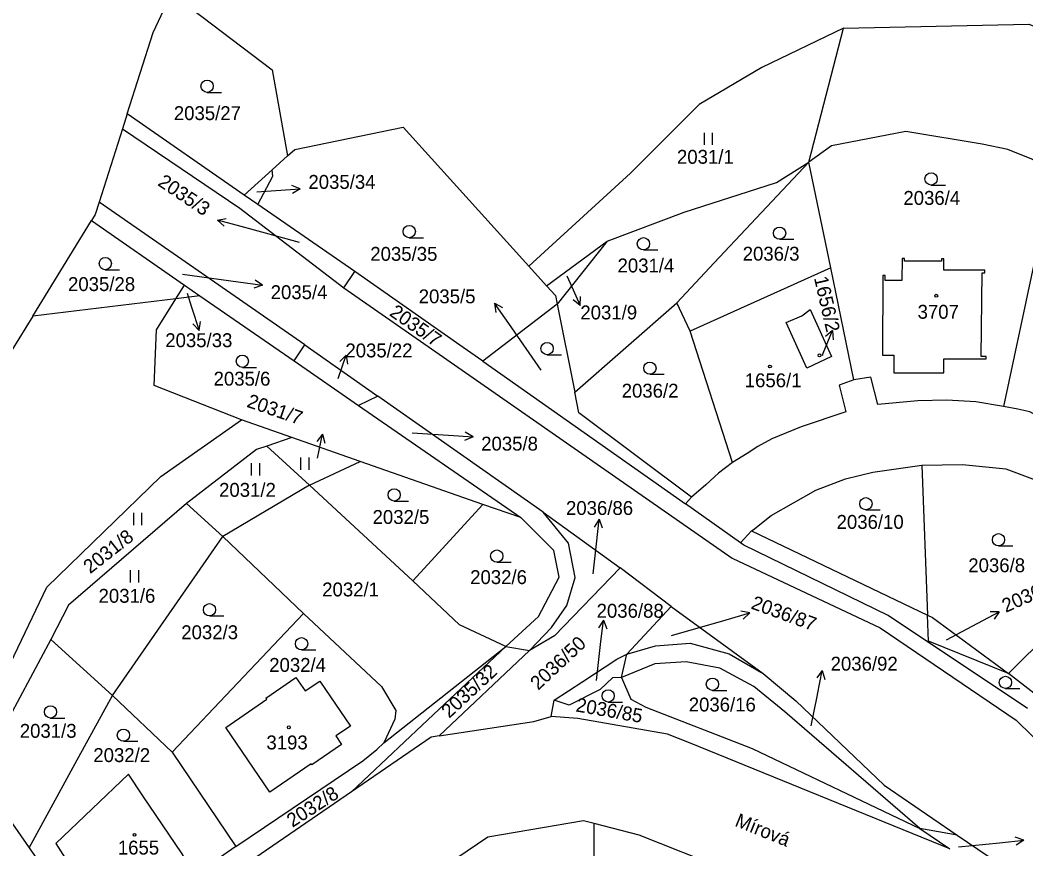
# Model space of a CAD drawing. Extents: x -667048 to -665920, y -1108425 to -1107247.
# Drawn here: x -666139.7 to -666016.5, y -1107726.9 to -1107625.4 of the extents above; entities that cross this region are included whole.
import ezdxf

# ---------------------------------------------------------------- set-up
doc = ezdxf.new("R2010")
doc.units = 0
for name, color, linetype in [('Default', 7, 'Continuous'), ('Hranice parcel', 7, 'Continuous'), ('Parcelní čísla', 7, 'Continuous'), ('Pop_ PČ_ popisy', 7, 'Continuous'), ('Značky budov', 7, 'Continuous'), ('Značky kultur', 7, 'Continuous')]:
    doc.layers.add(name, color=color, linetype=linetype)

# ---------------------------------------------------------------- blocks, each defined once
blk = doc.blocks.new('3.041')
at = {"layer": 'Default'}
blk.add_line((8, 0), (1758, 0), dxfattribs=at)
blk.add_circle((8, 750), 750, dxfattribs=at)
blk = doc.blocks.new('4.021')
at = {"layer": 'Default'}
blk.add_circle((-7, 1), 175, dxfattribs=at)
blk = doc.blocks.new('10291')
at = {"layer": 'Default'}
for p, q in [((0, 3001), (-500, 2001)), ((0, 1), (0, 3001)), ((0, 3001), (500, 2001))]:
    blk.add_line(p, q, dxfattribs=at)
blk = doc.blocks.new('3.061')
at = {"layer": 'Default'}
for p, q in [((-511, -1), (-511, 1499)), ((489, -1), (489, 1499))]:
    blk.add_line(p, q, dxfattribs=at)

msp = doc.modelspace()

# ---------------------------------------------------------------- linework, layer by layer
at = {"layer": 'Hranice parcel'}
for points in [[(-666126.55, -1107636.9), (-666123.38, -1107626.94), (-666121.14, -1107622.11)], [(-666121.14, -1107622.11), (-666108.79, -1107631.49), (-666106.92, -1107642.04)], [(-666038.82, -1107626.38), (-666048.84, -1107631.2), (-666056.53, -1107635.73), (-666064.94, -1107644.13)], [(-666043.09, -1107642.81), (-666038.82, -1107626.38)], [(-666038.82, -1107626.38), (-666016.14, -1107625.93), (-665994.09, -1107634.39), (-665981.04, -1107650.44)], [(-666126.55, -1107636.9), (-666127.14, -1107638.72)], [(-666112.23, -1107646.85), (-666126.55, -1107636.9)], [(-666127.14, -1107638.72), (-666130, -1107647.71)], [(-666127.14, -1107638.72), (-666112.76, -1107648.43)], [(-666106.92, -1107642.04), (-666106.03, -1107641.24), (-666092.76, -1107638.5)], [(-666092.76, -1107638.5), (-666077.38, -1107655.53)], [(-666013.02, -1107643.67), (-666015.77, -1107642.42), (-666018.71, -1107641.25), (-666021.85, -1107640.59), (-666031.19, -1107639.05), (-666040.31, -1107640.81), (-666043.09, -1107642.81)], [(-666108.8, -1107643.74), (-666106.92, -1107642.04)], [(-666067.77, -1107652.47), (-666058.33, -1107648.93), (-666047.06, -1107645.31), (-666043.09, -1107642.81)], [(-666059.25, -1107660.01), (-666054.69, -1107655.12), (-666043.09, -1107642.81)], [(-666040.4, -1107655.74), (-666043.09, -1107642.81)], [(-666112.23, -1107646.85), (-666108.8, -1107643.74)], [(-666110.56, -1107648), (-666108.71, -1107644.5), (-666108.8, -1107643.74)], [(-666064.94, -1107644.13), (-666077.38, -1107655.53)], [(-666130, -1107647.71), (-666130.48, -1107649.22), (-666130.92, -1107649.94)], [(-666104.81, -1107665.18), (-666130, -1107647.71)], [(-666110.56, -1107648), (-666112.23, -1107646.85)], [(-666112.76, -1107648.43), (-666100.03, -1107658.18)], [(-666098.67, -1107656.18), (-666110.56, -1107648)], [(-666138.14, -1107661.65), (-666130.92, -1107649.94)], [(-666130.92, -1107649.94), (-666119.55, -1107657.87)], [(-666075.19, -1107657.95), (-666067.77, -1107652.47)], [(-666067.77, -1107652.47), (-666073.91, -1107660.17)], [(-666015.18, -1107653.76), (-666019.23, -1107672.73)], [(-666026.85, -1107654.93), (-666031.38, -1107654.91), (-666031.38, -1107654.61), (-666031.67, -1107654.61), (-666031.68, -1107657.3), (-666033.72, -1107657.29), (-666033.72, -1107656.69), (-666034.02, -1107656.69), (-666034.05, -1107666.44), (-666032.66, -1107666.44), (-666032.67, -1107668.58), (-666026.55, -1107668.6), (-666026.55, -1107666.86), (-666021.38, -1107666.88), (-666021.38, -1107666.58), (-666021.97, -1107666.58), (-666021.84, -1107656.34), (-666021.54, -1107656.34), (-666021.54, -1107656.04), (-666026.56, -1107656.02), (-666026.55, -1107654.63), (-666026.85, -1107654.63), (-666026.85, -1107654.93)], [(-666100.03, -1107658.18), (-666098.67, -1107656.18)], [(-666083.01, -1107667.18), (-666085.41, -1107665.49), (-666098.67, -1107656.18)], [(-666077.38, -1107655.53), (-666075.19, -1107657.95)], [(-666040.4, -1107655.74), (-666057.62, -1107663.5)], [(-666037.56, -1107669.44), (-666040.4, -1107655.74)], [(-666120.59, -1107659.54), (-666119.55, -1107657.87)], [(-666119.55, -1107657.87), (-666117.65, -1107659.18)], [(-666100.03, -1107658.18), (-666087.4, -1107666.97), (-666052.47, -1107691.28)], [(-666075.19, -1107657.95), (-666074.12, -1107659.13), (-666073.91, -1107660.17)], [(-666120.59, -1107659.54), (-666138.14, -1107661.65)], [(-666112.57, -1107674.36), (-666123.25, -1107670.16), (-666122.96, -1107663.32), (-666120.59, -1107659.54)], [(-666117.65, -1107659.18), (-666120.59, -1107659.54)], [(-666117.65, -1107659.18), (-666106.13, -1107667.13)], [(-666073.91, -1107660.17), (-666083.01, -1107667.18)], [(-666073.91, -1107660.17), (-666071.74, -1107670.97)], [(-666071.74, -1107670.97), (-666059.25, -1107660.01)], [(-666057.62, -1107663.5), (-666059.25, -1107660.01)], [(-666043.95, -1107661.62), (-666042.91, -1107660.83), (-666040.29, -1107666.6), (-666043.31, -1107668.03), (-666045.84, -1107662.42), (-666043.95, -1107661.62)], [(-666138.14, -1107661.65), (-666140.71, -1107665.82)], [(-666052.42, -1107679.56), (-666057.62, -1107663.5)], [(-666106.13, -1107667.13), (-666104.81, -1107665.18)], [(-666104.81, -1107665.18), (-666095.86, -1107671.46)], [(-666106.13, -1107667.13), (-666098.22, -1107672.6)], [(-666083.01, -1107667.18), (-666058.2, -1107684.64)], [(-666037.56, -1107669.44), (-666039.38, -1107670.11), (-666038.56, -1107673.36), (-666044, -1107675.19), (-666047.63, -1107676.66), (-666049.32, -1107677.61), (-666050.62, -1107678.47), (-666052.42, -1107679.56)], [(-666019.23, -1107672.73), (-666022.62, -1107672.14), (-666026.18, -1107671.94), (-666029.73, -1107672.04), (-666034.64, -1107672.46), (-666035.47, -1107669.11), (-666037.56, -1107669.44)], [(-666071.24, -1107673.47), (-666071.74, -1107670.97)], [(-666095.86, -1107671.46), (-666098.22, -1107672.6)], [(-666075.63, -1107685.64), (-666095.86, -1107671.46)], [(-666098.22, -1107672.6), (-666078.34, -1107686.32)], [(-666057.45, -1107683.83), (-666071.24, -1107673.47)], [(-666006.82, -1107677.45), (-666008.51, -1107676.59), (-666010.53, -1107675.64), (-666012.61, -1107674.8), (-666014.86, -1107673.96), (-666016.01, -1107673.37), (-666017.49, -1107673.04), (-666019.23, -1107672.73)], [(-666167.42, -1107754.08), (-666155.7, -1107735.31), (-666147.1, -1107717.09), (-666136.4, -1107694.81), (-666122.43, -1107681.29), (-666112.57, -1107674.36)], [(-666106.38, -1107676.52), (-666112.57, -1107674.36)], [(-666106.38, -1107676.52), (-666109.46, -1107677.56)], [(-666098.02, -1107679.44), (-666106.38, -1107676.52)], [(-666109.46, -1107677.56), (-666110.74, -1107677.99), (-666119.29, -1107684.58)], [(-666104.23, -1107682.36), (-666109.46, -1107677.56)], [(-666104.23, -1107682.36), (-666098.02, -1107679.44)], [(-666083.01, -1107684.69), (-666098.02, -1107679.44)], [(-666052.42, -1107679.56), (-666054.14, -1107680.89), (-666055.69, -1107682.29), (-666057.45, -1107683.83)], [(-666050.1, -1107687.95), (-666049.9, -1107687.81), (-666047.68, -1107686.06), (-666042.22, -1107682.95), (-666038.57, -1107681.58), (-666035.25, -1107680.76), (-666029.24, -1107679.91)], [(-666029.24, -1107679.91), (-666024.27, -1107679.81), (-666018.96, -1107680.36), (-666014.38, -1107682.04), (-666009.79, -1107684.43), (-666006.01, -1107687.29), (-666003.21, -1107690.1)], [(-666029.24, -1107679.91), (-666028.55, -1107698.26)], [(-666104.23, -1107682.36), (-666114.85, -1107688.62)], [(-666091.6, -1107694.05), (-666104.23, -1107682.36)], [(-666119.29, -1107684.58), (-666133.75, -1107697.04), (-666135.93, -1107701.24)], [(-666119.29, -1107684.58), (-666114.85, -1107688.62)], [(-666083.01, -1107684.69), (-666091.6, -1107694.05)], [(-666078.34, -1107686.32), (-666083.01, -1107684.69)], [(-666058.2, -1107684.64), (-666057.45, -1107683.83)], [(-666051.43, -1107689.4), (-666058.2, -1107684.64)], [(-666075.63, -1107685.64), (-666066.18, -1107692.48)], [(-666074.58, -1107699.75), (-666072.73, -1107697.07), (-666071.71, -1107693.64), (-666072.52, -1107689.46), (-666075.63, -1107685.64)], [(-666076.2, -1107698.42), (-666073.65, -1107693.6), (-666074.32, -1107690.36), (-666078.34, -1107686.32)], [(-666051.43, -1107689.4), (-666050.1, -1107687.95)], [(-666050.1, -1107687.95), (-666028.55, -1107698.26)], [(-666128.38, -1107708.08), (-666114.85, -1107688.62)], [(-666114.85, -1107688.62), (-666104.96, -1107698.04)], [(-666051.05, -1107689.67), (-666051.43, -1107689.4)], [(-666016.3, -1107709.69), (-666033.36, -1107698.28), (-666051.05, -1107689.67)], [(-666018.63, -1107705.41), (-666003.21, -1107690.1)], [(-666052.47, -1107691.28), (-666034.33, -1107699.82), (-666017.67, -1107711.11), (-666005.73, -1107722.82), (-666004.06, -1107724)], [(-666066.18, -1107692.48), (-666074.23, -1107700.79), (-666077.31, -1107702.57)], [(-666059.95, -1107697.19), (-666066.18, -1107692.48)], [(-666085.85, -1107699.46), (-666091.6, -1107694.05)], [(-666065.38, -1107703.05), (-666059.95, -1107697.19)], [(-666059.95, -1107697.19), (-666048.67, -1107705.38)], [(-666104.96, -1107698.04), (-666121.05, -1107715.01)], [(-666104.96, -1107698.04), (-666095.43, -1107707)], [(-666080.18, -1107702.08), (-666076.2, -1107698.42)], [(-666028.43, -1107701.44), (-666028.55, -1107698.26)], [(-666028.55, -1107698.26), (-666027.95, -1107698.55)], [(-666080.18, -1107702.08), (-666085.85, -1107699.46)], [(-666027.95, -1107698.55), (-666018.63, -1107705.41)], [(-666077.31, -1107702.57), (-666074.58, -1107699.75)], [(-666135.93, -1107701.24), (-666144.8, -1107717.8)], [(-666128.38, -1107708.08), (-666135.93, -1107701.24)], [(-666099.11, -1107719.88), (-666090.43, -1107711.72), (-666080.18, -1107702.08)], [(-666095.12, -1107713.89), (-666080.18, -1107702.08)], [(-666080.18, -1107702.08), (-666077.31, -1107702.57)], [(-666065.38, -1107703.05), (-666061.85, -1107702.03)], [(-666061.85, -1107702.03), (-666057.61, -1107701.7), (-666052.82, -1107702.99), (-666048.67, -1107705.38)], [(-666018.63, -1107705.41), (-666028.43, -1107701.44)], [(-666077.31, -1107702.57), (-666088.35, -1107713.04)], [(-666066.59, -1107703.65), (-666065.38, -1107703.05)], [(-666066.02, -1107705.88), (-666065.38, -1107703.05)], [(-666074.28, -1107708.66), (-666070.76, -1107706.36), (-666066.59, -1107703.65)], [(-666061.94, -1107704.2), (-666066.02, -1107705.88)], [(-666029.5, -1107724.39), (-666046.01, -1107710.11), (-666049.83, -1107706.97), (-666053.98, -1107704.75), (-666058.1, -1107703.97), (-666061.94, -1107704.2)], [(-666048.67, -1107705.38), (-666044.66, -1107708.74), (-666033.86, -1107719.07), (-666024.91, -1107725.17)], [(-666006.95, -1107714.45), (-666018.63, -1107705.41)], [(-666114.49, -1107712.02), (-666109.47, -1107708.56), (-666109.57, -1107708.41), (-666105.9, -1107705.89), (-666104.77, -1107707.54), (-666102.99, -1107706.33), (-666099.23, -1107711.83), (-666101, -1107713.04), (-666100.31, -1107714.08), (-666103.96, -1107716.59), (-666104.05, -1107716.47), (-666109.08, -1107719.92), (-666114.49, -1107712.02)], [(-666095.43, -1107707), (-666093.67, -1107709.94), (-666093.77, -1107710.99)], [(-666067.12, -1107705.93), (-666068.62, -1107707.34), (-666072.44, -1107709.28), (-666074.28, -1107708.66)], [(-666066.02, -1107705.88), (-666067.12, -1107705.93)], [(-666066.02, -1107705.88), (-666064.87, -1107708.54), (-666063.03, -1107709.51)], [(-666138.58, -1107726.74), (-666132.93, -1107716.4), (-666128.38, -1107708.08)], [(-666121.05, -1107715.01), (-666128.38, -1107708.08)], [(-666074.64, -1107710.65), (-666074.28, -1107708.66)], [(-666063.03, -1107709.51), (-666050.03, -1107714.59), (-666029.5, -1107724.39)], [(-666076.77, -1107711.29), (-666074.64, -1107710.65)], [(-666060.4, -1107712.81), (-666071.38, -1107710.9), (-666074.64, -1107710.65)], [(-666093.77, -1107710.99), (-666095.12, -1107713.89)], [(-666088.35, -1107713.04), (-666076.77, -1107711.29)], [(-666088.35, -1107713.04), (-666089.35, -1107713.19), (-666099.11, -1107719.88)], [(-666025.82, -1107726.88), (-666057.69, -1107713.89), (-666060.4, -1107712.81)], [(-666095.98, -1107714.69), (-666095.12, -1107713.89)], [(-666121.05, -1107715.01), (-666113.24, -1107726.58)], [(-666113.24, -1107726.58), (-666097.72, -1107716.1), (-666095.98, -1107714.69)], [(-666144.8, -1107717.8), (-666138.58, -1107726.74)], [(-666118.31, -1107730.07), (-666119.84, -1107727.48), (-666124.64, -1107720.36), (-666126.41, -1107717.74), (-666135.31, -1107726.22), (-666128.39, -1107737.02)], [(-666099.11, -1107719.88), (-666160.69, -1107762.11)], [(-666070.67, -1107723.43), (-666082.41, -1107725.44)], [(-666069.37, -1107723.76), (-666070.67, -1107723.43)], [(-666032.37, -1107737.69), (-666063.88, -1107725.17), (-666069.37, -1107723.76)], [(-666069.32, -1107753.84), (-666069.37, -1107723.76)], [(-666082.41, -1107725.44), (-666105.42, -1107741.01)], [(-666029.5, -1107724.39), (-666025.82, -1107726.88)], [(-666024.91, -1107725.17), (-666029.5, -1107724.39)], [(-666024.91, -1107725.17), (-666017.32, -1107730.34)], [(-666138.58, -1107726.74), (-666130.44, -1107738.43)], [(-666113.24, -1107726.58), (-666118.31, -1107730.07)]]:
    msp.add_lwpolyline(points, dxfattribs=at)
at = {"layer": 'Pop_ PČ_ popisy'}
for points in [[(-666110.7, -1107646.44), (-666108.36, -1107646.28)], [(-666105.47, -1107652.62), (-666112.62, -1107650.69)], [(-666119.8, -1107656.5), (-666112.96, -1107657.46)], [(-666072.71, -1107656.71), (-666072.3, -1107657.62)], [(-666119.23, -1107658.82), (-666118.67, -1107660.55)], [(-666075.88, -1107668.25), (-666079.84, -1107662.54)], [(-666041.42, -1107666.45), (-666041.32, -1107666.2)], [(-666091.68, -1107675.94), (-666087.2, -1107676.22)], [(-666069.48, -1107693.21), (-666069.08, -1107689.51)], [(-666059.91, -1107700.74), (-666053.19, -1107698.81)], [(-666026.23, -1107701.26), (-666022.4, -1107699.25)], [(-666069.1, -1107706.26), (-666068.58, -1107701.86)], [(-666042.78, -1107711.8), (-666042.01, -1107707.99)], [(-666024.74, -1107726.63), (-666019.74, -1107726.12)]]:
    msp.add_lwpolyline(points, dxfattribs=at)

# ---------------------------------------------------------------- block references
for p, xscale, yscale, rotation in [((-666108.36, -1107646.28), 0.0010000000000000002, 0.0010000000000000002, -85.99999996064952), ((-666112.62, -1107650.69), 0.0010000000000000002, 0.0010000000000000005, 75.00000002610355), ((-666112.96, -1107657.46), 0.0010000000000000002, 0.001, -97.99999994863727), ((-666072.3, -1107657.62), 0.0010000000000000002, 0.0010000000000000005, -156.000000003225), ((-666079.84, -1107662.54), 0.001, 0.0010000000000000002, 34.99999999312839), ((-666118.67, -1107660.55), 0.001, 0.001, -162.00000009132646), ((-666041.32, -1107666.2), 0.0010000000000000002, 0.001, -21.99999993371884), ((-666100.72, -1107669.27), 0.001, 0.0010000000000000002, -19.00000009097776), ((-666103.26, -1107679.05), 0.001, 0.0010000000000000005, -12.000000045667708), ((-666087.2, -1107676.22), 0.0010000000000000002, 0.0010000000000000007, -93.99999998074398), ((-666069.08, -1107689.51), 0.001, 0.001, -5.999999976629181), ((-666053.19, -1107698.81), 0.0009999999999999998, 0.0010000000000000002, -73.99999993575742), ((-666022.4, -1107699.25), 0.001, 0.0010000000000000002, -61.99999998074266), ((-666068.58, -1107701.86), 0.0010000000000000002, 0.0010000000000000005, -6.999999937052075), ((-666042.01, -1107707.99), 0.001, 0.0010000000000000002, -10.999999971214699), ((-666019.74, -1107726.12), 0.001, 0.0009999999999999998, -84.00000003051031)]:
    msp.add_blockref('10291', p, dxfattribs=dict(at, xscale=xscale, yscale=yscale, rotation=rotation))
at = {"layer": 'Značky budov', "xscale": 0.0010000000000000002, "yscale": 0.0010000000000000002}
for p in [(-666027.46, -1107659.15), (-666041.77, -1107666.45), (-666047.83, -1107667.82), (-666106.76, -1107711.99), (-666125.67, -1107725.15)]:
    msp.add_blockref('4.021', p, dxfattribs=at)
at = {"layer": 'Značky kultur', "xscale": 0.0010000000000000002, "yscale": 0.0010000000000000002}
for name, p in [('3.041', (-666116.79, -1107634.26)), ('3.061', (-666055.35, -1107640.7)), ('3.041', (-666028.12, -1107645.61)), ('3.041', (-666092.02, -1107652.05)), ('3.041', (-666046.67, -1107652.24)), ('3.041', (-666063.35, -1107653.54)), ('3.041', (-666129.25, -1107655.97)), ('3.041', (-666075.15, -1107666.38)), ('3.041', (-666112.47, -1107667.92)), ('3.041', (-666062.55, -1107668.77)), ('3.061', (-666110.81, -1107681.16)), ('3.061', (-666104.77, -1107680.47)), ('3.041', (-666093.87, -1107684.29)), ('3.041', (-666036.1, -1107685.36)), ('3.061', (-666125.24, -1107687.23)), ('3.041', (-666019.86, -1107689.77)), ('3.041', (-666081.31, -1107691.77)), ('3.061', (-666125.63, -1107694.25)), ('3.041', (-666116.49, -1107698.34)), ('3.041', (-666105.21, -1107702.5)), ('3.041', (-666019.01, -1107707.23)), ('3.041', (-666054.9, -1107707.46)), ('3.041', (-666067.67, -1107708.89)), ('3.041', (-666135.96, -1107710.85)), ('3.041', (-666127.03, -1107713.7))]:
    msp.add_blockref(name, p, dxfattribs=at)

# ---------------------------------------------------------------- texts
at = {"layer": 'Parcelní čísla'}
for s, p in [('2035/27', (-666120.85, -1107637.65)), ('2031/1', (-666059.23, -1107643)), ('2035/34', (-666104.37, -1107646.07)), ('2036/4', (-666031.5, -1107648.03)), ('2035/35', (-666096.79, -1107654.88)), ('2036/3', (-666051.18, -1107654.86)), ('2031/4', (-666066.51, -1107656.3)), ('2035/28', (-666133.81, -1107658.58)), ('2035/4', (-666108.99, -1107659.57)), ('2035/5', (-666090.86, -1107660.08)), ('2031/9', (-666071.06, -1107662.05)), ('3707', (-666029.76, -1107661.97)), ('2035/33', (-666121.9, -1107665.45)), ('2035/22', (-666099.84, -1107666.7)), ('2035/6', (-666115.98, -1107670.16)), ('1656/1', (-666050.93, -1107670.36)), ('2036/2', (-666066, -1107671.63)), ('2035/8', (-666083.21, -1107678.11)), ('2031/2', (-666115.31, -1107683.77)), ('2036/86', (-666072.82, -1107685.99)), ('2032/5', (-666096.51, -1107687.09)), ('2036/10', (-666039.68, -1107687.69)), ('2036/8', (-666023.55, -1107693)), ('2032/6', (-666084.56, -1107694.45)), ('2032/1', (-666102.68, -1107695.96)), ('2031/6', (-666130.07, -1107696.74)), ('2036/88', (-666069.07, -1107698.57)), ('2032/3', (-666119.94, -1107701.2)), ('2036/92', (-666040.41, -1107705.05)), ('2032/4', (-666109.17, -1107705.2)), ('2036/16', (-666057.79, -1107710.05)), ('2031/3', (-666139.72, -1107713.27)), ('3193', (-666109.51, -1107714.69)), ('2032/2', (-666130.71, -1107716.24)), ('1655', (-666127.71, -1107727.56))]:
    msp.add_text(s, height=1.7, dxfattribs=at).set_placement(p)
for s, rotation, p in [('2035/3', 326, (-666122.93, -1107645.57)), ('1656/2', 283, (-666042.46, -1107656.97)), ('2035/7', 325, (-666094.55, -1107661.5)), ('2031/7', 341, (-666112.02, -1107672.73)), ('2031/8', 38, (-666131.1, -1107693.25)), ('2036/93', 24, (-666018.96, -1107697.98)), ('2036/87', 340, (-666050.27, -1107697.42)), ('2036/50', 43, (-666076.23, -1107707.52)), ('2035/32', 43, (-666087.12, -1107710.95)), ('2036/85', 350, (-666071.7, -1107710.03)), ('2032/8', 33, (-666106.32, -1107724.3))]:
    msp.add_text(s, height=1.7, rotation=rotation, dxfattribs=at).set_placement(p)
at = {"layer": 'Pop_ PČ_ popisy'}
msp.add_text('Mírová', height=1.7, rotation=338, dxfattribs=at).set_placement((-666052.25, -1107724.03))

doc.saveas('drawing.dxf')
